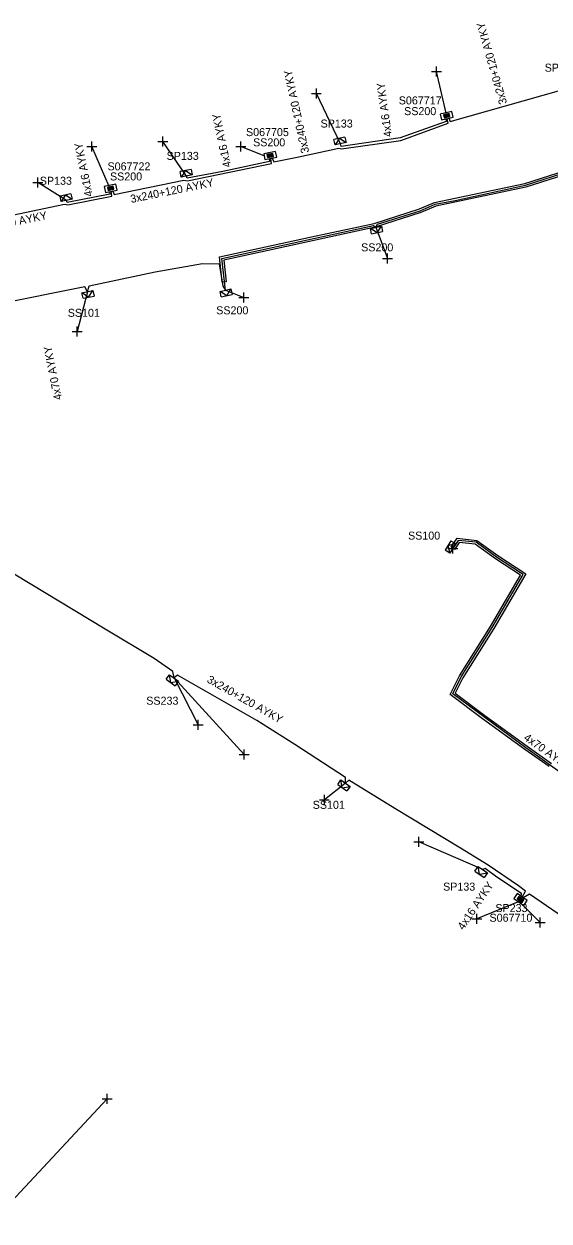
# Model space of a CAD drawing. Extents: x -748492 to -735633, y -1146251 to -1139940.
# Drawn here: x -736771.7 to -736706.1, y -1145045.1 to -1144895.6 of the extents above; entities that cross this region are included whole.
import ezdxf

# ---------------------------------------------------------------- set-up
doc = ezdxf.new("R2010")
doc.units = 0
for name, color, linetype in [('Vrstva 1', 7, 'Continuous'), ('Vrstva 20', 7, 'Continuous'), ('Vrstva 28', 7, 'Continuous'), ('Vrstva 29', 7, 'Continuous'), ('Vrstva 30', 7, 'Continuous'), ('Vrstva 31', 7, 'Continuous'), ('Vrstva 33', 7, 'Continuous'), ('Vrstva 34', 7, 'Continuous'), ('Vrstva 5', 7, 'Continuous'), ('Vrstva 52', 7, 'Continuous'), ('Vrstva 54', 7, 'Continuous'), ('Vrstva 59', 7, 'Continuous'), ('Vrstva 6', 7, 'Continuous'), ('Vrstva 8', 7, 'Continuous'), ('Vrstva 9', 7, 'Continuous')]:
    doc.layers.add(name, color=color, linetype=linetype)

# ---------------------------------------------------------------- blocks, each defined once
blk = doc.blocks.new('NN800')
at = {"layer": 'Vrstva 1'}
for points in [[(-0.44, 0.44), (0.44, -0.44)], [(-0.44, -0.44), (0.44, 0.44)]]:
    blk.add_lwpolyline(points, dxfattribs=at)
blk = doc.blocks.new('NN620')
at = {"layer": 'Vrstva 8'}
for points in [[(0.75, 0), (-0.75, 0)], [(-0.75, 0), (-0.75, -0.75)], [(0.75, -0.75), (0.75, 0)], [(-0.75, -0.75), (0.75, -0.75)], [(0.37, -0.18), (-0.38, -0.18)], [(-0.38, -0.18), (-0.38, -0.56)], [(-0.38, -0.56), (0.37, -0.56)], [(0.32, -0.23), (-0.33, -0.23)], [(-0.33, -0.23), (-0.33, -0.51)], [(-0.33, -0.51), (0.32, -0.51)], [(0.27, -0.27), (-0.28, -0.27)], [(-0.28, -0.27), (-0.28, -0.46)], [(-0.28, -0.46), (0.27, -0.46)], [(0.23, -0.32), (-0.23, -0.32)], [(-0.23, -0.32), (-0.23, -0.42)], [(-0.23, -0.42), (0.23, -0.42)], [(-0.19, -0.37), (0.19, -0.37)], [(0.23, -0.42), (0.23, -0.32)], [(0.27, -0.46), (0.27, -0.27)], [(0.32, -0.51), (0.32, -0.23)], [(0.37, -0.56), (0.37, -0.18)]]:
    blk.add_lwpolyline(points, dxfattribs=at)
blk = doc.blocks.new('NN630')
at = {"layer": 'Vrstva 9'}
for points in [[(0, -0.7), (-0.7, 0)], [(-0.7, -0.7), (-0.7, 0), (0.7, 0), (0.7, -0.7)], [(-0.7, -0.7), (0.7, -0.7)], [(0, -0.7), (0.7, 0)]]:
    blk.add_lwpolyline(points, dxfattribs=at)

msp = doc.modelspace()

# ---------------------------------------------------------------- linework, layer by layer
at = {"layer": 'Vrstva 20'}
msp.add_lwpolyline([(-736680.31, -1144905.93), (-736685.3, -1144907.91), (-736692.77, -1144910.79), (-736708.94, -1144915.96), (-736720.2, -1144918.33), (-736722.06, -1144919.12), (-736727.78, -1144920.96), (-736735.61, -1144922.66), (-736746.67, -1144925.07), (-736746.38, -1144927.76), (-736746.88, -1144927.82), (-736747.21, -1144924.67), (-736735.72, -1144922.17), (-736727.91, -1144920.48), (-736722.24, -1144918.66), (-736720.35, -1144917.85), (-736709.06, -1144915.48), (-736692.93, -1144910.31), (-736685.48, -1144907.44), (-736680.49, -1144905.47)], close=True, dxfattribs=at)
msp.add_lwpolyline([(-736706.04, -1144988.35), (-736709.09, -1144986.21), (-736714.36, -1144982.37), (-736718.41, -1144979.33), (-736717.25, -1144977.02), (-736713.37, -1144970.83), (-736709.62, -1144964.44), (-736712.75, -1144962.4), (-736715.27, -1144960.57), (-736717.3, -1144960.35), (-736717.88, -1144961.23), (-736718.3, -1144960.95), (-736717.54, -1144959.82), (-736715.09, -1144960.09), (-736712.47, -1144961.98), (-736708.95, -1144964.28), (-736712.95, -1144971.09), (-736716.81, -1144977.26), (-736717.77, -1144979.18), (-736714.06, -1144981.97), (-736708.8, -1144985.81), (-736705.74, -1144987.95)], dxfattribs=at)
at = {"layer": 'Vrstva 5'}
for points in [[(-736718.58, -1144907.32), (-736718.41, -1144907.73), (-736704.57, -1144903.83), (-736703.83, -1144903.78), (-736700.82, -1144902.99), (-736693.6, -1144901.08), (-736693.84, -1144900.42)], [(-736763.73, -1144929.01), (-736763.5, -1144928.29), (-736755.28, -1144926.55), (-736749.37, -1144925.48), (-736747.27, -1144925.51), (-736746.81, -1144928.32), (-736746.48, -1144928.83), (-736746.94, -1144924.87), (-736741.02, -1144923.59), (-736727.99, -1144920.75), (-736727.69, -1144920.96), (-736727.48, -1144920.59), (-736722.15, -1144918.89), (-736720.28, -1144918.09), (-736717.79, -1144917.6), (-736709, -1144915.72), (-736703.28, -1144913.88), (-736692.85, -1144910.55), (-736680.4, -1144905.7), (-736680.11, -1144906.29)], [(-736740.66, -1144912.31), (-736740.44, -1144912.79), (-736737.32, -1144912.15), (-736732.31, -1144911.06), (-736732, -1144911.15), (-736724.56, -1144910.1), (-736718.65, -1144907.95), (-736718.77, -1144907.38)], [(-736760.56, -1144916.41), (-736760.41, -1144916.86), (-736751.69, -1144915.08), (-736751.21, -1144915.14), (-736740.73, -1144913.01), (-736740.82, -1144912.36)], [(-736817.91, -1144915.36), (-736817.46, -1144915.82), (-736818.47, -1144926.84), (-736817.59, -1144927.16), (-736813.01, -1144926.55), (-736802.23, -1144925.18), (-736797.64, -1144924.26), (-736797.49, -1144923.67), (-736797.07, -1144924.14), (-736782.14, -1144921.34), (-736781.98, -1144920.76), (-736781.9, -1144921.28), (-736766.6, -1144918.09), (-736766.2, -1144918.17), (-736760.68, -1144917.07), (-736760.76, -1144916.47)], [(-736709.4, -1145004.65), (-736709, -1145003.94), (-736709.86, -1145003.27), (-736713.64, -1145000.66), (-736717.12, -1144998.53), (-736725.34, -1144993.61), (-736731.05, -1144990.05), (-736731.49, -1144990.42), (-736731.48, -1144989.71), (-736737.81, -1144985.59), (-736742.55, -1144982.58), (-736752.46, -1144976.94), (-736752.91, -1144977.28), (-736753.05, -1144976.49), (-736755.41, -1144974.84), (-736761.52, -1144971.19), (-736774.72, -1144963.21), (-736776.07, -1144962.65), (-736776.75, -1144962.78)], [(-736693.94, -1145015.45), (-736693.79, -1145015.11), (-736693.53, -1145014.86), (-736697.48, -1145011.97), (-736702.78, -1145008.22), (-736708.5, -1145004.28), (-736709.27, -1145004.74)]]:
    msp.add_lwpolyline(points, dxfattribs=at)
at = {"layer": 'Vrstva 52'}
for points in [[(-736718.97, -1144907.42), (-736718.92, -1144907.74), (-736724.64, -1144909.8), (-736732.04, -1144910.85), (-736732.1, -1144910.52)], [(-736741.01, -1144912.38), (-736740.99, -1144912.75), (-736746.81, -1144913.98), (-736751.27, -1144914.84), (-736751.34, -1144914.56)], [(-736760.98, -1144916.49), (-736760.92, -1144916.81), (-736766.26, -1144917.87), (-736766.33, -1144917.6)], [(-736763.73, -1144929.01), (-736764.07, -1144928.41), (-736775.09, -1144930.63), (-736775.36, -1144931.38)], [(-736683.47, -1144983.91), (-736684.22, -1144985.04), (-736680.93, -1144986.01), (-736682.41, -1144989.06), (-736684.51, -1144991.44), (-736689.73, -1144994.57), (-736692.04, -1144997.74), (-736696.74, -1144994.77), (-736703.82, -1144989.66), (-736708.95, -1144986.01), (-736718.09, -1144979.26), (-736717.03, -1144977.14), (-736713.16, -1144970.96), (-736709.29, -1144964.36), (-736709.62, -1144964.15), (-736712.61, -1144962.19), (-736715.18, -1144960.33), (-736717.42, -1144960.09), (-736718.09, -1144961.09)], [(-736709.54, -1145004.58), (-736709.51, -1145004.23), (-736712.59, -1145002.16), (-736714.03, -1145001.07), (-736714.34, -1145001.23)]]:
    msp.add_lwpolyline(points, dxfattribs=at)
at = {"layer": 'Vrstva 59'}
for points in [[(-736718.92, -1144906.72), (-736720.13, -1144901.5)], [(-736732.1, -1144910.52), (-736735.13, -1144904.25)], [(-736761.03, -1144915.85), (-736763.19, -1144910.88)], [(-736751.34, -1144914.56), (-736754.31, -1144910.25)], [(-736741.55, -1144912.07), (-736744.56, -1144910.88)], [(-736766.33, -1144917.6), (-736769.94, -1144915.38)], [(-736727.69, -1144920.96), (-736726.25, -1144924.88)], [(-736763.73, -1144929.01), (-736765, -1144934)], [(-736746.48, -1144928.83), (-736744.19, -1144929.75)], [(-736752.91, -1144977.28), (-736744.16, -1144986.86)], [(-736752.91, -1144977.28), (-736749.88, -1144983.13)], [(-736731.49, -1144990.42), (-736734.13, -1144992.5)], [(-736714.34, -1145001.23), (-736722.31, -1144997.75)], [(-736709.78, -1145005.22), (-736715.06, -1145007.38)], [(-736709.78, -1145005.22), (-736707.16, -1145007.85)], [(-736775.55, -1145045.14), (-736761.25, -1145029.88)]]:
    msp.add_lwpolyline(points, dxfattribs=at)

# ---------------------------------------------------------------- block references
at = {"layer": 'Vrstva 28'}
for p, rotation in [((-736718.77, -1144907.38), -166.8490501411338), ((-736740.82, -1144912.36), -168.262222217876), ((-736760.76, -1144916.47), -168.33000551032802), ((-736709.4, -1145004.65), -34.70842218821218)]:
    msp.add_blockref('NN620', p, dxfattribs=dict(at, rotation=rotation))
at = {"layer": 'Vrstva 31'}
for p, rotation in [((-736732.1, -1144910.52), -167.79088048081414), ((-736751.34, -1144914.56), -168.7022304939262), ((-736766.33, -1144917.6), -168.26142791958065), ((-736727.69, -1144920.96), 12.037202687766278), ((-736763.73, -1144929.01), 11.61632504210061), ((-736746.48, -1144928.83), 13.206755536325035), ((-736718.09, -1144961.09), -121.72063616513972), ((-736752.91, -1144977.28), -35.74122511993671), ((-736731.49, -1144990.42), -35.00656951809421), ((-736714.34, -1145001.23), -34.426477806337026)]:
    msp.add_blockref('NN630', p, dxfattribs=dict(at, rotation=rotation))
at = {"layer": 'Vrstva 34'}
for p, rotation in [((-736720.13, -1144901.5), 45), ((-736735.13, -1144904.25), 45), ((-736754.31, -1144910.25), 45), ((-736763.19, -1144910.88), 44.99999995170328), ((-736744.56, -1144910.88), 45), ((-736769.94, -1144915.38), 44.99999995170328), ((-736726.25, -1144924.88), 45), ((-736744.19, -1144929.75), 44.99999995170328), ((-736765, -1144934), 45), ((-736718.09, -1144961.09), 45), ((-736749.88, -1144983.13), 45), ((-736744.16, -1144986.86), 44.99999995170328), ((-736734.13, -1144992.5), 45), ((-736722.31, -1144997.75), 45), ((-736715.06, -1145007.38), 45), ((-736707.16, -1145007.85), 45), ((-736761.25, -1145029.88), 45)]:
    msp.add_blockref('NN800', p, dxfattribs=dict(at, rotation=rotation))

# ---------------------------------------------------------------- texts
at = {"layer": 'Vrstva 29'}
for s, p in [('S067717', (-736724.83, -1144905.61)), ('S067705', (-736743.92, -1144909.57)), ('S067722', (-736761.22, -1144913.85)), ('S067710', (-736713.49, -1145007.74))]:
    msp.add_text(s, height=1, dxfattribs=at).set_placement(p)
at = {"layer": 'Vrstva 30'}
for s, p in [('SS200', (-736724.16, -1144906.95)), ('SS200', (-736743.03, -1144910.85)), ('SS200', (-736760.91, -1144915.11)), ('SP233', (-736712.76, -1145006.53))]:
    msp.add_text(s, height=1, dxfattribs=at).set_placement(p)
at = {"layer": 'Vrstva 33'}
for s, p in [('SP133', (-736706.6, -1144901.52)), ('SP133', (-736734.6, -1144908.5)), ('SP133', (-736753.84, -1144912.54)), ('SP133', (-736769.68, -1144915.65)), ('SS200', (-736729.53, -1144923.97)), ('SS200', (-736747.64, -1144931.84)), ('SS101', (-736766.19, -1144932.15)), ('SS100', (-736723.67, -1144959.99)), ('SS233', (-736756.38, -1144980.62)), ('SS101', (-736735.58, -1144993.63)), ('SP133', (-736719.29, -1145003.85))]:
    msp.add_text(s, height=1, dxfattribs=at).set_placement(p)
at = {"layer": 'Vrstva 54'}
for s, rotation, p in [('4x16 AYKY', 98.048, (-736725.67, -1144909.61)), ('4x16 AYKY', 101.933, (-736745.77, -1144913.37)), ('4x16 AYKY', 101.256, (-736763.06, -1144917.03)), ('4x70 AYKY', 101.39, (-736766.9, -1144942.44)), ('4x70 AYKY', 325.033, (-736709.31, -1144984.95)), ('4x16 AYKY', 56.096, (-736716.75, -1145008.85))]:
    msp.add_text(s, height=1, rotation=rotation, dxfattribs=at).set_placement(p)
at = {"layer": 'Vrstva 6'}
for rotation, p in [(105.705, (-736711.29, -1144905.45)), (102.058, (-736736.02, -1144911.59)), (11.519, (-736758.26, -1144917.93)), (11.754, (-736779.07, -1144922.08)), (330.355, (-736748.89, -1144977.76))]:
    msp.add_text('3x240+120 AYKY', height=1, rotation=rotation, dxfattribs=at).set_placement(p)

doc.saveas('drawing.dxf')
